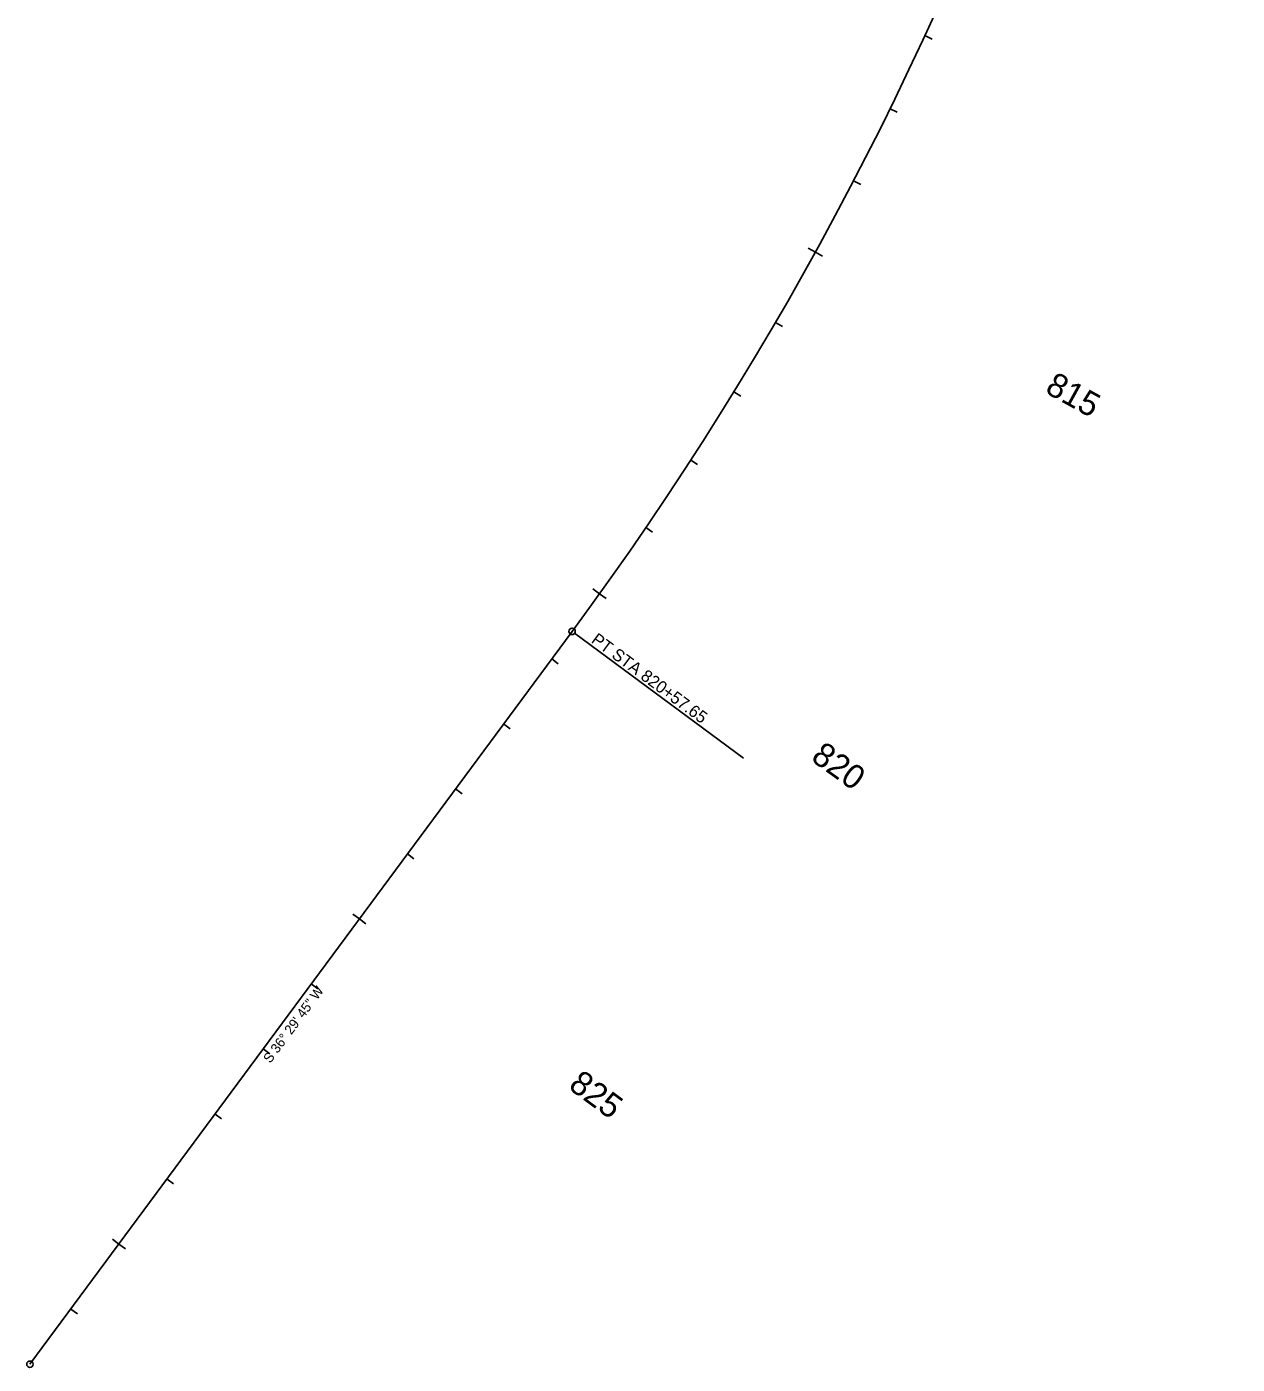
# Model space of a CAD drawing. Extents: x 2819977 to 2827606, y 116785 to 150320.
# Drawn here: x 2822204 to 2823701, y 136089 to 137743 of the extents above; entities that cross this region are included whole.
import ezdxf

# ---------------------------------------------------------------- set-up
doc = ezdxf.new("R2010")
doc.units = 0
for name, color, linetype in [('Default', 7, 'Continuous'), ('Roadway-Centerline main', 7, 'Continuous'), ('Roadway-Curve pc pt', 7, 'Continuous'), ('Text-Alignment info', 7, 'Continuous')]:
    doc.layers.add(name, color=color, linetype=linetype)

msp = doc.modelspace()

# ---------------------------------------------------------------- linework, layer by layer
at = {"layer": 'Default'}
msp.add_line((2822878.3, 136994.9), (2822207.8, 136088.7), dxfattribs=at)
msp.add_arc((2819501.9, 139492.9), 4200, 323.5041, 358.849, dxfattribs=at)
at = {"layer": 'Roadway-Centerline main'}
for p, q in [((2823314.7, 137731.5), (2823323.8, 137727.3)), ((2823271.7, 137641.2), (2823280.6, 137636.8)), ((2823226.5, 137552), (2823235.4, 137547.4)), ((2823179.3, 137463.9), (2823170.5, 137468.7)), ((2823179.3, 137463.9), (2823188, 137459)), ((2823129.9, 137376.9), (2823138.5, 137371.9)), ((2823078.5, 137291.1), (2823087, 137285.9)), ((2823025.1, 137206.6), (2823033.5, 137201.1)), ((2822969.6, 137123.4), (2822977.9, 137117.7)), ((2822912.2, 137041.5), (2822904.1, 137047.3)), ((2822912.2, 137041.5), (2822920.4, 137035.6)), ((2822878.3, 136994.9), (2822207.8, 136088.7)), ((2822853.1, 136960.9), (2822861.1, 136954.9)), ((2822793.6, 136880.5), (2822801.6, 136874.5)), ((2822734.1, 136800.1), (2822742.2, 136794.1)), ((2822674.7, 136719.7), (2822682.7, 136713.7)), ((2822615.2, 136639.3), (2822607.1, 136645.2)), ((2822615.2, 136639.3), (2822623.2, 136633.3)), ((2822555.7, 136558.9), (2822563.7, 136553)), ((2822496.2, 136478.5), (2822504.3, 136472.6)), ((2822436.8, 136398.1), (2822444.8, 136392.2)), ((2822377.3, 136317.7), (2822385.3, 136311.8)), ((2822317.8, 136237.3), (2822309.8, 136243.3)), ((2822317.8, 136237.3), (2822325.8, 136231.4)), ((2822258.3, 136157), (2822266.4, 136151))]:
    msp.add_line(p, q, dxfattribs=at)
msp.add_arc((2819501.9, 139492.9), 4200, 323.5041, 358.849, dxfattribs=at)
at = {"layer": 'Roadway-Curve pc pt'}
msp.add_line((2822881.5, 136992.5), (2823090.3, 136838), dxfattribs=at)
for centre in [(2822878.3, 136994.9), (2822207.8, 136088.7)]:
    msp.add_circle(centre, 4, dxfattribs=at)

# ---------------------------------------------------------------- texts
at = {"layer": 'Roadway-Centerline main'}
for s, rotation, p in [(' 815', 331.1114, (2823452.2, 137296.1)), (' 820', 324.2905, (2823163.3, 136842.5)), (' 825', 323.5041, (2822863.5, 136436.9))]:
    msp.add_text(s, height=30, rotation=rotation, dxfattribs=at).set_placement(p)
at = {"layer": 'Roadway-Curve pc pt'}
msp.add_text('PT STA 820+57.65', height=15, rotation=323.5041, dxfattribs=at).set_placement((2822901, 136981.9))
at = {"layer": 'Text-Alignment info'}
msp.add_text('S 36%%d 29\' 45" W', height=12, rotation=53.5041, dxfattribs=at).set_placement((2822505, 136460.1))

doc.saveas('drawing.dxf')
